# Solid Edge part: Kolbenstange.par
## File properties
Username: ahadarics
Dokumentum tartalom típus: 0
Author: ahadarics
Last saved by: ahadarics
Revision: 86
Sűrűség: 0,000 kg/m^3
Pontosság: 0,990
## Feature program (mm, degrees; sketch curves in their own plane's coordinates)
base feature "unnamed BaseFeature 1"
thread "unnamed Thread 1"
chamfer "Letörés_1" setback 0.7
sketch for "Kihúzás_1" plane through (57.5, 0, 0) normal (1, 0, 0) x-axis (0, 1, 0)
  circle centre (0, 0) radius 12.5
extrude "Kihúzás_1" add finite 27 along -normal
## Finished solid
Body 1: solid body, 13 faces, 23 edges, 12 vertices.
  Faces by surface: plane 9, cylinder 3, cone 1
  Edges by curve: line 12, circle 11
Bounding box of the edges (mm): 494.500 x 25.000 x 25.000, from (-437, -12.5, -12.5) to (57.5, 12.5, 12.5).
Cylindrical faces by radius (mm): R5 x2, R12.5 x1
Conical faces (half-angle, radius in mm at the cone's reference point): 45 deg R4.3 x1
Planar faces by outward normal: +x 3, +z 1, -x 4, -z 1
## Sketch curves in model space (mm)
circle centre (57.5, 0, 0) radius 12.5
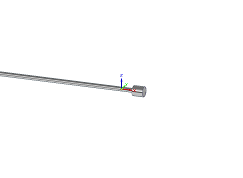
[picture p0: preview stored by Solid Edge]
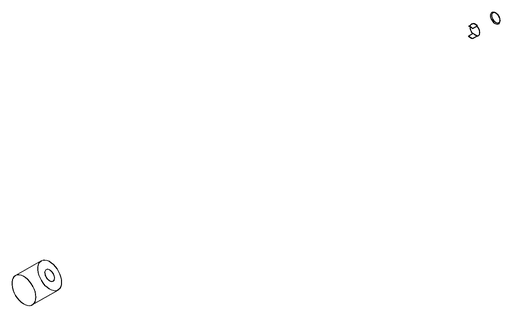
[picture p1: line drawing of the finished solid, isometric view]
